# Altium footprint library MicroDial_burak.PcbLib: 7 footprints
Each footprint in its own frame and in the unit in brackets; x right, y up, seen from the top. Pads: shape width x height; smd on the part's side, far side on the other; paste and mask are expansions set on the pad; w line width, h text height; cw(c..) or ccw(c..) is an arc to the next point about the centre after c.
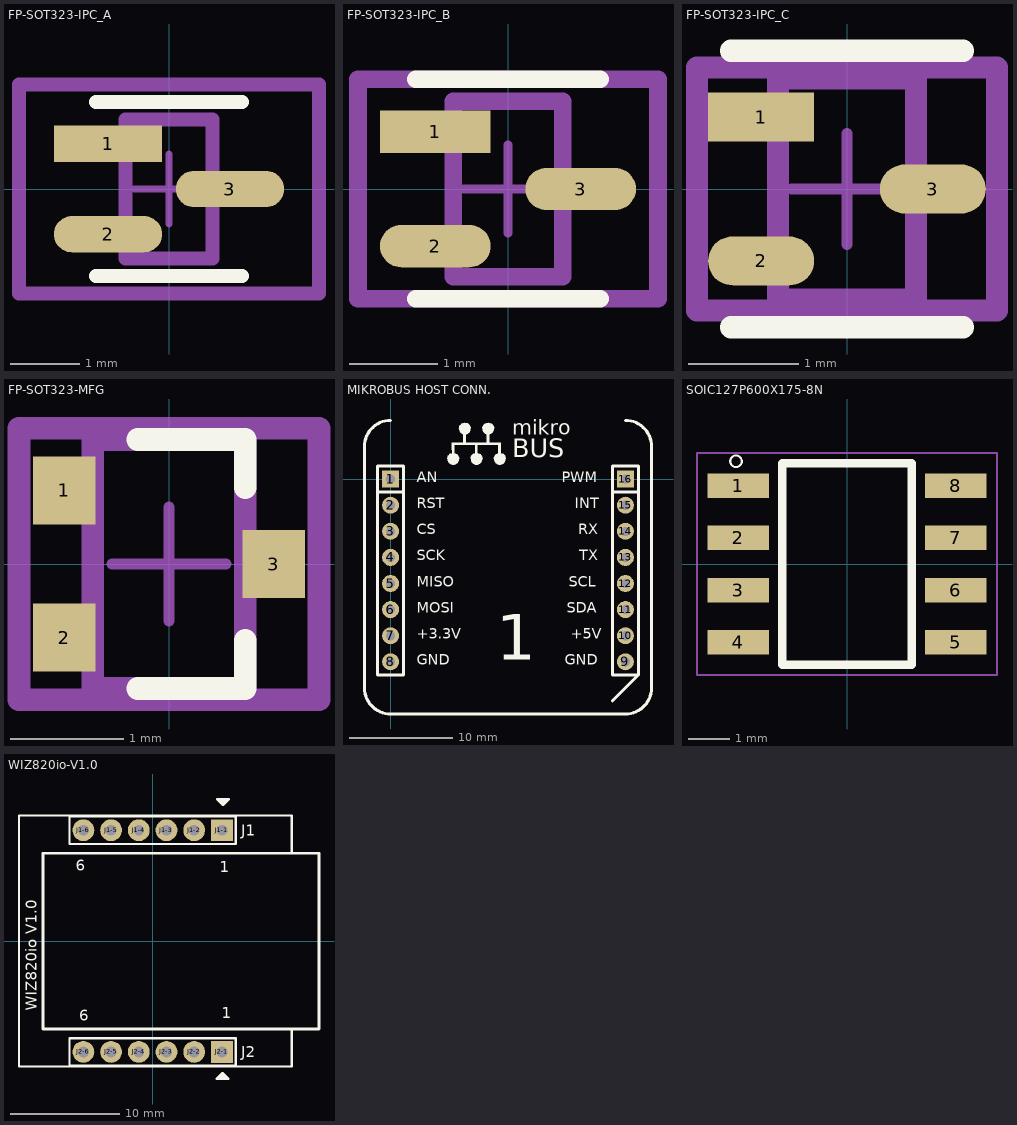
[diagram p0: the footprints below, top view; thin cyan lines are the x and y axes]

## FP-SOT323-IPC_A [mm]
pads (3):
  rect 1.559x0.522 smd paste+0 mask+0: 1(-0.877,0.65)
  rrect100% 1.559x0.522 smd paste+0 mask+0: 2(-0.877,-0.65) 3(0.877,0)
Top Overlay:
  lines w0.2: -1.05,-1.25 1.05,-1.25 ; -1.05,1.25 1.05,1.25
Mechanical 5:
  lines w0.2: -2.156,-1.5 -2.156,1.5 2.156,1.5 2.156,-1.5 -2.156,-1.5
  text ".Designator" at 0,0.188 h1
Mechanical 13:
  lines w0.2: -0.625,-1 -0.625,1 0.625,1 0.625,-1 -0.625,-1
Mechanical 15:
  lines w0.2: -2.156,-1.5 -2.156,1.5 2.156,1.5 2.156,-1.5 -2.156,-1.5
Mechanical 16:
  lines w0.1: -0.5,0 0.5,0 ; 0,-0.5 0,0.5

## FP-SOT323-IPC_B [mm]
pads (3):
  rect 1.259x0.482 smd paste+0 mask+0: 1(-0.827,0.65)
  rrect100% 1.259x0.482 smd paste+0 mask+0: 2(-0.827,-0.65) 3(0.827,0)
Top Overlay:
  lines w0.2: -1.05,-1.25 1.05,-1.25 ; -1.05,1.25 1.05,1.25
Mechanical 5:
  lines w0.2: -1.706,-1.25 -1.706,1.25 1.706,1.25 1.706,-1.25 -1.706,-1.25
  text ".Designator" at 0,0.188 h1
Mechanical 13:
  lines w0.2: -0.625,-1 -0.625,1 0.625,1 0.625,-1 -0.625,-1
Mechanical 15:
  lines w0.2: -1.706,-1.25 -1.706,1.25 1.706,1.25 1.706,-1.25 -1.706,-1.25
Mechanical 16:
  lines w0.1: -0.5,0 0.5,0 ; 0,-0.5 0,0.5

## FP-SOT323-IPC_C [mm]
pads (3):
  rect 0.959x0.442 smd paste+0 mask+0: 1(-0.777,0.65)
  rrect100% 0.959x0.442 smd paste+0 mask+0: 2(-0.777,-0.65) 3(0.777,0)
Top Overlay:
  lines w0.2: -1.05,-1.25 1.05,-1.25 ; -1.05,1.25 1.05,1.25
Mechanical 5:
  lines w0.2: -1.356,-1.1 -1.356,1.1 1.356,1.1 1.356,-1.1 -1.356,-1.1
  text ".Designator" at 0,0.188 h1
Mechanical 13:
  lines w0.2: -0.625,-1 -0.625,1 0.625,1 0.625,-1 -0.625,-1
Mechanical 15:
  lines w0.2: -1.356,-1.1 -1.356,1.1 1.356,1.1 1.356,-1.1 -1.356,-1.1
Mechanical 16:
  lines w0.1: -0.5,0 0.5,0 ; 0,-0.5 0,0.5

## FP-SOT323-MFG [mm]
pads (3):
  rect 0.55x0.6 smd paste-1000 mask+0: 1(-0.925,0.65) 2(-0.925,-0.65) 3(0.925,0)
Top Overlay:
  lines w0.2: -0.275,-1.1 0.675,-1.1 0.675,-0.675 ; -0.275,1.1 0.675,1.1 0.675,0.675
Top Paste:
  rectangle: 0.65,-0.25 1.2,0.25
  rectangle: -1.2,-0.9 -0.65,-0.4
  rectangle: -1.2,0.4 -0.65,0.9
Mechanical 5:
  lines w0.2: -1.325,-1.2 -1.325,1.2 1.325,1.2 1.325,-1.2 -1.325,-1.2
  text ".Designator" at 0,-0.001 h1
Mechanical 13:
  lines w0.2: -0.675,-1.1 -0.675,1.1 0.675,1.1 0.675,-1.1 -0.675,-1.1
Mechanical 15:
  lines w0.2: -1.325,-1.2 -1.325,1.2 1.325,1.2 1.325,-1.2 -1.325,-1.2
Mechanical 16:
  lines w0.1: -0.5,0 0.5,0 ; 0,-0.5 0,0.5
3D body "Diode_Nexperia_PESD1CAN-UX_eec.STEP": height 0.25, standoff 0, extent -1.2,-1.325 1.2,1.325

## MIKROBUS HOST CONN. [mil]
height 47.24
pads (16):
  rect 65x65 hole 35: 1(0,0) 16(900,0)
  round 65 hole 35: 2(0,-100) 3(0,-200) 4(0,-300) 5(0,-400) 6(0,-500) 7(0,-600) 8(0,-700) 9(900,-700) 10(900,-600) 11(900,-500) 12(900,-400) 13(900,-300) 14(900,-200) 15(900,-100)
Top Overlay:
  drawing of 650 lines, arcs and shapes, not listed
  text "SDA" at 674.28,-525 h70
  text "RST" at 100,-125 h70
  text "CS" at 100,-225 h70
  text "MISO" at 100,-425 h70
  text "SCK" at 100,-325 h70
  text "MOSI" at 100,-525 h70
  text "+3.3V" at 100,-625 h70
  text "GND" at 100,-725 h70
  text "SCL" at 683.48,-425 h70
  text "INT" at 706.49,-125 h70
  text "RX" at 718.67,-225 h70
  text "TX" at 722.17,-325 h70
  text "GND" at 668,-725 h70
  text "+5V" at 691,-625 h70
  text "AN" at 100,-25 h70
  text "PWM" at 656.79,-25 h70
  text "mikro" at 467,150.54 h99
  text "BUS" at 467,58.51 h121.5
  text "1" at 405,-750 h300
Bottom Overlay:
  drawing of 645 lines, arcs and shapes, not listed
  text "mikro" at 430,170 h110
  text "BUS" at 430,60 h135
  text "PWM" at 800,-25 h70
  text "+5V" at 800,-625 h70
  text "GND" at 800,-725 h70
  text "TX" at 800,-325 h70
  text "RX" at 800,-225 h70
  text "INT" at 800,-125 h70
  text "SCL" at 800,-425 h70
  text "SDA" at 800,-525 h70
  text "AN" at 180.36,-25 h70
  text "GND" at 230,-725 h70
  text "+3.3V" at 260,-625 h70
  text "MOSI" at 248.27,-525 h70
  text "SCK" at 224.23,-325 h70
  text "MISO" at 251.12,-425 h70
  text "CS" at 179,-225 h70
  text "RST" at 217.49,-125 h70
  text "1" at 485,-750 h300
3D body "F1X8.stp": height 334.65, standoff -124.02, extent 850.79,-754.92 949.21,54.92
3D body "F1X8.stp": height 334.65, standoff -124.02, extent -49.21,-754.92 49.21,54.92

## SOIC127P600X175-8N [mm]
pads (8):
  rect 1.5x0.6 smd: 1(-2.65,1.905) 2(-2.65,0.635) 3(-2.65,-0.635) 4(-2.65,-1.905) 5(2.65,-1.905) 6(2.65,-0.635) 7(2.65,0.635) 8(2.65,1.905)
Top Overlay:
  circle w0.05: c-2.7,2.5 r0.141
  lines w0.2: -1.575,-2.45 -1.575,2.45 1.575,2.45 1.575,-2.45 -1.575,-2.45
Mechanical 15:
  lines w0.05: -3.65,-2.7 -3.65,2.7 3.65,2.7 3.65,-2.7 -3.65,-2.7

## WIZ820io-V1.0 [mm] "WIZ820io module Ethernet V1.0"
pads (12):
  rect 2x2 hole 1: J1-1(6.35,10.16) J2-1(6.35,-10.16)
  round 2 hole 1: J1-2(3.81,10.16) J1-3(1.27,10.16) J1-4(-1.27,10.16) J1-5(-3.81,10.16) J1-6(-6.35,10.16) J2-2(3.81,-10.16) J2-3(1.27,-10.16) J2-4(-1.27,-10.16) J2-5(-3.81,-10.16) J2-6(-6.35,-10.16)
Top Overlay:
  region: 5.954,13 6.97,13 6.462,12.492
  region: 6.908,-12.622 5.892,-12.622 6.4,-12.114
  lines w0.2: 12.75,-8.05 12.75,-11.5 -12.25,-11.5 -12.25,11.5 12.75,11.5 12.75,8.05 ; -7.62,-11.41 -7.62,-8.91 7.62,-8.91 7.62,-11.41 -7.62,-11.41 ; -7.62,8.91 -7.62,11.41 7.62,11.41 7.62,8.91 -7.62,8.91
  lines w0.254: 15.225,-8.05 -10.049,-8.05 -10.049,8.05 15.25,8.05 15.25,-8.05 ; 5.892,-12.622 6.4,-12.114 6.908,-12.622 5.892,-12.622 ; 5.954,13 6.97,13 6.462,12.492 5.954,13
  text "1" at 6.146,6.301 h1
  text "J1" at 8.128,9.652 h1
  text "1" at 6.35,-7.066 h1
  text "6" at -6.746,-7.32 h1
  text "WIZ820io V1.0" at -10.618,-6.399 h1
  text "J2" at 8.128,-10.668 h1
  text "6" at -7.062,6.428 h1
3D body "M20-7820642.stp": height 8.5, standoff -3, extent -7.82,8.91 7.82,11.41
3D body "M20-7820642.stp": height 8.5, standoff -3, extent -7.82,-11.41 7.82,-8.91
3D body "WIZ820IO.STEP": height 28.11, standoff 2.4, extent -12.15,-11.5 15.35,11.5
